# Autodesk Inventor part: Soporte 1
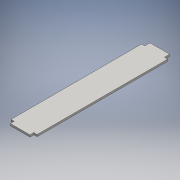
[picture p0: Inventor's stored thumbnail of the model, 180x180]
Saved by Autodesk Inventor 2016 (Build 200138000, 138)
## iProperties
Created: 2016-06
Part Number: Soporte 1
Material: Genérico
Document SubType Name: Modeling
Designer: adm
Density: 1 g/cm^3
Appearance: Valor por defecto
Author: adm
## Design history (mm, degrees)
sketch "Boceto1"
  geometry: L1 (40, 0)-(40, -200); L2 (0, -200)-(0, 0); L3 (5, 0)-(5, 8); L4 (5, 8)-(35, 8); L5 (35, 8)-(35, 0); L6 (35, -200)-(35, -206); L7 (35, -206)-(5, -206); L8 (5, -206)-(5, -200); L9 (40, -200)-(35, -200); L10 (5, -200)-(0, -200); L11 (0, 0)-(5, 0); L12 (35, 0)-(40, 0)
  constraints: 24 end point, 7 parallel, 2 horizontal, 2 perpendicular
  dimensions: "d0" = 200 distance of L1.start L1.end; "d1" = 40 distance of L2.end L1.start; "d2" = 30 distance of L3.end L4.end; "d3" = 5 distance between parallel lines of L2 L3; "d5" = 5 distance between parallel lines of L1 L6; "d6" = 30 distance of L6.end L7.end
extrude "Extrusión1" new body sketch "Boceto1" distance "d8" = 3; taper "d9" = 0 deg
node "Sólido1"
other parameters: "d4" = 8, "d7" = 6
